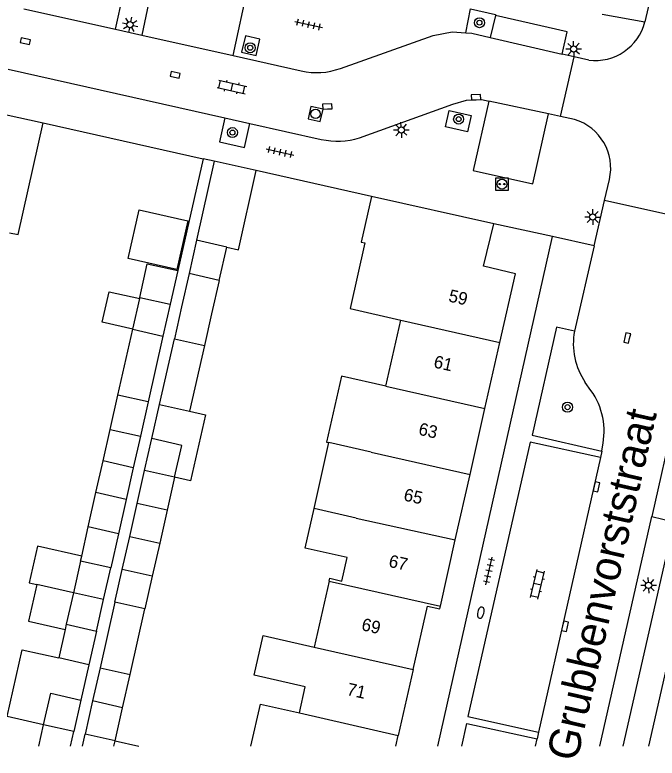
# Model space of a CAD drawing. Extents: x 128000 to 131008, y 398996 to 402500.
# Drawn here: x 128768.7 to 128820, y 398999 to 399058.4 of the extents above; entities that cross this region are included whole.
import ezdxf

# ---------------------------------------------------------------- set-up
doc = ezdxf.new("R2010")
doc.units = 0
for name, color, linetype in [('gg-afsc-muur', 7, 'Continuous'), ('gg-anno-huisnummerreeks BGT', 7, 'Continuous'), ('gg-anno-openbare ruimte label', 7, 'Continuous'), ('gg-bbg-bijgebouw', 7, 'Continuous'), ('gg-bbg-gedigitaliseerde bebouwing', 7, 'Continuous'), ('gg-bbg-gedigitaliseerde bijgebouw', 7, 'Continuous'), ('gg-bbg-hoofdgebouw', 7, 'Continuous'), ('gg-bbg-luifel en loopbrug', 7, 'Continuous'), ('gg-bbg-tussenscheiding', 7, 'Continuous'), ('gg-knt-verharding', 7, 'Continuous'), ('gg-knt-verharding nz', 7, 'Continuous'), ('gt-grn-weggrens', 7, 'Continuous'), ('gt-symb-boom', 7, 'Continuous'), ('gt-symb-brandkraan', 7, 'Continuous'), ('gt-symb-klinker verharding', 7, 'Continuous'), ('gt-symb-kolk', 7, 'Continuous'), ('gt-symb-laadpunt elektrisch vervoer', 7, 'Continuous'), ('gt-symb-lichtmast', 7, 'Continuous'), ('gt-symb-rioolschacht', 7, 'Continuous'), ('gt-symb-tegel verharding', 7, 'Continuous')]:
    doc.layers.add(name, color=color, linetype=linetype)

# ---------------------------------------------------------------- blocks, each defined once
blk = doc.blocks.new('gt0-TEG1')
at = {"layer": 'gt-symb-tegel verharding'}
for p, q in [((-1.125, 0), (1.125, 0)), ((-0.9, -0.25), (-0.9, 0.25)), ((-0.45, -0.25), (-0.45, 0.25)), ((0, -0.25), (0, 0.25)), ((0.45, -0.25), (0.45, 0.25)), ((0.9, -0.25), (0.9, 0.25))]:
    blk.add_line(p, q, dxfattribs=at)
blk = doc.blocks.new('gt0-BOOM')
at = {"layer": 'gt-symb-boom'}
for radius in [0.4, 0.2]:
    blk.add_circle((0, 0), radius, dxfattribs=at)
blk = doc.blocks.new('gt0-LMAST')
at = {"layer": 'gt-symb-lichtmast'}
for p, q in [((-0.005, 0.246), (-0.005, 0.621)), ((-0.182, 0.173), (-0.447, 0.438)), ((0.172, 0.173), (0.437, 0.438)), ((-0.255, -0.004), (-0.63, -0.004)), ((-0.182, -0.181), (-0.447, -0.446)), ((-0.005, -0.254), (-0.005, -0.629)), ((0.437, -0.446), (0.172, -0.181)), ((0.245, -0.004), (0.62, -0.004))]:
    blk.add_line(p, q, dxfattribs=at)
blk.add_circle((-0.005, -0.004), 0.25, dxfattribs=at)
blk = doc.blocks.new('gt0-KOLK')
at = {"layer": 'gt-symb-kolk'}
blk.add_lwpolyline([(0, 0), (0.375, 0), (0.375, 0.4), (-0.375, 0.4), (-0.375, 0), (0, 0)], dxfattribs=at)
blk = doc.blocks.new('gt0-BR')
at = {"layer": 'gt-symb-brandkraan'}
for centre, radius, start, end in [((-0.244, 0), 0.206, 107.56694, 252.43307), ((0.599, -2.664), 3, 106.89205, 107.56694), ((0, -0.691), 0.938, 73.10799, 106.89205), ((-0.599, -2.664), 3, 72.43309, 73.10799), ((0.244, 0), 0.206, 287.56695, 72.43309), ((0.599, 2.664), 3, 252.43307, 253.10797), ((0, 0.691), 0.938, 253.10797, 286.89206), ((-0.599, 2.664), 3, 286.89206, 287.56695)]:
    blk.add_arc(centre, radius, start, end, dxfattribs=at)
blk = doc.blocks.new('gt0-KL1')
at = {"layer": 'gt-symb-klinker verharding'}
for p, q in [((-1.15, 0.3), (1.15, 0.3)), ((-1, -0.3), (-1, 0.3)), ((-0.5, 0.3), (-0.5, 0.45)), ((0, -0.3), (0, 0.3)), ((0.5, 0.3), (0.5, 0.45)), ((1, -0.3), (1, 0.3)), ((-1.15, -0.3), (1.15, -0.3)), ((-0.5, -0.45), (-0.5, -0.3)), ((0.5, -0.45), (0.5, -0.3))]:
    blk.add_line(p, q, dxfattribs=at)
blk = doc.blocks.new('gt0-LEV')
at = {"layer": 'gt-symb-laadpunt elektrisch vervoer'}
blk.add_lwpolyline([(-0.486, 0.501), (0.486, 0.501), (0.486, -0.499), (-0.486, -0.499)], close=True, dxfattribs=at)
for centre, radius in [((0, 0), 0.393), ((-0.186, 0), 0.0566), ((0.186, 0), 0.0566)]:
    blk.add_circle(centre, radius, dxfattribs=at)
blk = doc.blocks.new('gt0-RS')
at = {"layer": 'gt-symb-rioolschacht'}
blk.add_lwpolyline([(-0.5, -0.5), (0.5, -0.5), (0.5, 0.5), (-0.5, 0.5)], close=True, dxfattribs=at)
blk.add_circle((0, 0), 0.375, dxfattribs=at)

msp = doc.modelspace()

# ---------------------------------------------------------------- linework, layer by layer
at = {"layer": 'gg-afsc-muur'}
for p, q in [((128770.991, 399049.778), (128783.786, 399046.917)), ((128783.786, 399046.917), (128781.753, 399037.979)), ((128797.228, 399043.912), (128788.016, 399045.971))]:
    msp.add_line(p, q, dxfattribs=at)
at = {"layer": 'gg-bbg-bijgebouw'}
for p, q in [((128783.25, 399040.401), (128782.652, 399037.742)), ((128785.66, 399039.851), (128783.25, 399040.401)), ((128785.057, 399037.196), (128785.66, 399039.851)), ((128778.164, 399033.305), (128778.713, 399035.744)), ((128778.713, 399035.744), (128778.733, 399035.832)), ((128778.733, 399035.832), (128781.141, 399035.29)), ((128781.141, 399035.29), (128780.57, 399032.754)), ((128780.295, 399027.292), (128781.482, 399032.547)), ((128783.88, 399032.005), (128782.695, 399026.755)), ((128780.295, 399027.292), (128782.695, 399026.755)), ((128775.791, 399022.779), (128776.358, 399025.294)), ((128776.358, 399025.294), (128778.766, 399024.751)), ((128778.766, 399024.751), (128778.199, 399022.236)), ((128779.107, 399022.031), (128779.678, 399024.562)), ((128775.222, 399020.254), (128775.791, 399022.779)), ((128778.199, 399022.236), (128777.63, 399019.711)), ((128778.51, 399019.387), (128779.107, 399022.031)), ((128781.504, 399021.485), (128780.908, 399018.845)), ((128777.63, 399019.711), (128775.222, 399020.254)), ((128780.908, 399018.845), (128778.51, 399019.387)), ((128773.99, 399014.784), (128773.421, 399012.259)), ((128776.398, 399014.242), (128773.99, 399014.784)), ((128775.829, 399011.718), (128776.398, 399014.242)), ((128776.728, 399011.499), (128777.32, 399014.121)), ((128779.719, 399013.583), (128777.32, 399014.121)), ((128779.719, 399013.583), (128779.127, 399010.96)), ((128773.421, 399012.259), (128772.852, 399009.734)), ((128775.26, 399009.192), (128775.829, 399011.718)), ((128772.852, 399009.734), (128775.26, 399009.192)), ((128774.019, 399003.684), (128773.452, 399001.168)), ((128774.948, 399003.618), (128774.349, 399000.967)), ((128777.35, 399003.077), (128774.948, 399003.618)), ((128776.753, 399000.428), (128777.35, 399003.077)), ((128770.658, 399000), (128771.043, 399001.707)), ((128773.189, 399000), (128773.452, 399001.168)), ((128774.131, 399000), (128774.349, 399000.967)), ((128776.657, 399000), (128776.753, 399000.428))]:
    msp.add_line(p, q, dxfattribs=at)
for points in [[(128782.652, 399037.742), (128782.054, 399035.082), (128781.482, 399032.547)], [(128785.057, 399037.196), (128784.453, 399034.54), (128783.88, 399032.005)], [(128781.504, 399021.485), (128782.077, 399024.02), (128779.678, 399024.562)], [(128771.043, 399001.707), (128771.611, 399004.226), (128774.019, 399003.684)]]:
    msp.add_lwpolyline(points, dxfattribs=at)
at = {"layer": 'gg-bbg-gedigitaliseerde bebouwing'}
for p, q in [((128798.376, 399028.765), (128799.563, 399034.028)), ((128792.633, 399018.979), (128793.815, 399024.249)), ((128793.835, 399013.176), (128792.649, 399007.923))]:
    msp.add_line(p, q, dxfattribs=at)
for points in [[(128798.376, 399028.765), (128794.822, 399029.559), (128793.64, 399024.288), (128793.815, 399024.249)], [(128793.835, 399013.176), (128793.887, 399013.408), (128794.862, 399013.188), (128795.287, 399015.074), (128791.927, 399015.828), (128792.633, 399018.979)], [(128791.462, 399002.661), (128791.933, 399004.751), (128787.851, 399005.666), (128788.563, 399008.839), (128792.649, 399007.923)], [(128787.589, 399000), (128788.351, 399003.365), (128791.462, 399002.661)]]:
    msp.add_lwpolyline(points, dxfattribs=at)
at = {"layer": 'gg-bbg-gedigitaliseerde bijgebouw'}
for p, q in [((128776.979, 399028.048), (128778.164, 399033.305)), ((128780.57, 399032.754), (128779.387, 399027.505)), ((128779.387, 399027.505), (128776.979, 399028.048)), ((128773.421, 399012.259), (128770.494, 399012.918)), ((128776.728, 399011.499), (128775.547, 399006.268)), ((128777.947, 399005.726), (128779.127, 399010.96)), ((128772.852, 399009.734), (128772.762, 399009.332)), ((128775.547, 399006.268), (128777.947, 399005.726))]:
    msp.add_line(p, q, dxfattribs=at)
msp.add_lwpolyline([(128770.494, 399012.918), (128769.835, 399009.991), (128772.762, 399009.332)], dxfattribs=at)
at = {"layer": 'gg-bbg-hoofdgebouw'}
for p, q in [((128806.986, 399041.723), (128797.228, 399043.912)), ((128806.285, 399026.979), (128807.472, 399032.238)), ((128805.096, 399021.71), (128806.285, 399026.979)), ((128803.913, 399016.47), (128805.096, 399021.71)), ((128802.722, 399011.192), (128803.913, 399016.47)), ((128800.548, 399006.115), (128799.358, 399000.857)), ((128799.164, 399000), (128799.358, 399000.857))]:
    msp.add_line(p, q, dxfattribs=at)
for points in [[(128797.228, 399043.912), (128796.41, 399040.263), (128796.693, 399040.199), (128795.514, 399034.944), (128799.563, 399034.028)], [(128807.472, 399032.238), (128808.71, 399037.721), (128806.172, 399038.33), (128806.986, 399041.723)], [(128800.548, 399006.115), (128801.694, 399011.18), (128802.67, 399010.961), (128802.722, 399011.192)]]:
    msp.add_lwpolyline(points, dxfattribs=at)
at = {"layer": 'gg-bbg-luifel en loopbrug'}
for p, q in [((128767.98, 399050.451), (128770.991, 399049.778)), ((128784.664, 399046.721), (128783.25, 399040.401)), ((128788.016, 399045.971), (128784.664, 399046.721)), ((128781.753, 399037.979), (128781.141, 399035.29)), ((128776.358, 399025.294), (128776.979, 399028.048)), ((128779.387, 399027.505), (128778.766, 399024.751)), ((128779.678, 399024.562), (128780.295, 399027.292)), ((128774.605, 399017.515), (128775.222, 399020.254)), ((128777.63, 399019.711), (128777.013, 399016.973)), ((128777.913, 399016.743), (128778.51, 399019.387)), ((128780.908, 399018.845), (128780.312, 399016.206)), ((128774.08, 399015.186), (128774.605, 399017.515)), ((128777.013, 399016.973), (128774.605, 399017.515)), ((128777.013, 399016.973), (128776.398, 399014.242)), ((128777.32, 399014.121), (128777.913, 399016.743)), ((128777.913, 399016.743), (128780.312, 399016.206)), ((128780.312, 399016.206), (128779.719, 399013.583)), ((128773.99, 399014.784), (128774.08, 399015.186)), ((128772.762, 399009.332), (128772.246, 399007.045)), ((128775.26, 399009.192), (128774.654, 399006.503)), ((128774.654, 399006.503), (128772.246, 399007.045)), ((128774.654, 399006.503), (128774.019, 399003.684)), ((128775.547, 399006.268), (128774.948, 399003.618)), ((128777.35, 399003.077), (128777.947, 399005.726)), ((128776.753, 399000.428), (128778.648, 399000))]:
    msp.add_line(p, q, dxfattribs=at)
for points in [[(128768.319, 399041.011), (128769.002, 399040.859), (128770.991, 399049.778)], [(128785.66, 399039.851), (128786.597, 399039.637), (128788.016, 399045.971)], [(128777.783, 399038.946), (128778.662, 399042.848), (128782.564, 399041.97), (128781.686, 399038.067), (128777.783, 399038.946)], [(128778.733, 399035.832), (128779.314, 399038.528), (128781.753, 399037.979)], [(128778.164, 399033.305), (128775.725, 399033.854), (128776.274, 399036.293), (128778.713, 399035.744)], [(128782.695, 399026.755), (128783.962, 399026.467), (128782.766, 399021.198), (128781.504, 399021.485)], [(128774.08, 399015.186), (128770.545, 399015.982), (128769.886, 399013.055), (128770.494, 399012.918)], [(128771.043, 399001.707), (128768.116, 399002.366), (128769.319, 399007.705), (128772.246, 399007.045)]]:
    msp.add_lwpolyline(points, dxfattribs=at)
at = {"layer": 'gg-bbg-tussenscheiding'}
for p, q in [((128785.057, 399037.196), (128782.652, 399037.742)), ((128799.563, 399034.028), (128807.472, 399032.238)), ((128778.164, 399033.305), (128780.57, 399032.754)), ((128781.482, 399032.547), (128783.88, 399032.005)), ((128798.376, 399028.765), (128806.285, 399026.979)), ((128797.186, 399023.493), (128793.815, 399024.249)), ((128797.186, 399023.493), (128805.096, 399021.71)), ((128778.199, 399022.236), (128775.791, 399022.779)), ((128781.504, 399021.485), (128779.107, 399022.031)), ((128795.997, 399018.221), (128792.633, 399018.979)), ((128795.997, 399018.221), (128803.913, 399016.47)), ((128793.835, 399013.176), (128802.722, 399011.192)), ((128775.829, 399011.718), (128773.421, 399012.259)), ((128779.127, 399010.96), (128776.728, 399011.499)), ((128792.649, 399007.923), (128800.548, 399006.115)), ((128791.462, 399002.661), (128799.358, 399000.857)), ((128773.452, 399001.168), (128771.043, 399001.707)), ((128776.753, 399000.428), (128774.349, 399000.967))]:
    msp.add_line(p, q, dxfattribs=at)
at = {"layer": 'gg-knt-verharding'}
for p, q in [((128819.523, 399059.897), (128819.059, 399057.84)), ((128807.114, 399058.351), (128806.709, 399056.602)), ((128776.787, 399057.259), (128778.88, 399056.79)), ((128813.415, 399055.057), (128812.462, 399055.277)), ((128786.167, 399055.159), (128791.61, 399053.941)), ((128812.324, 399050.28), (128813.415, 399055.057)), ((128814.57, 399054.791), (128813.415, 399055.057)), ((128768.2, 399054.058), (128785.505, 399050.185)), ((128812.324, 399050.28), (128811.355, 399050.49)), ((128785.505, 399050.185), (128787.51, 399049.736)), ((128813.44, 399050.039), (128812.324, 399050.28)), ((128787.51, 399049.736), (128793.21, 399048.46)), ((128815.834, 399043.594), (128816.22, 399045.261)), ((128814.995, 399039.966), (128815.834, 399043.594)), ((128820.734, 399042.491), (128815.834, 399043.594)), ((128811.69, 399040.711), (128806.986, 399041.723)), ((128802.517, 399000), (128811.69, 399040.711)), ((128814.995, 399039.966), (128813.427, 399033.157)), ((128819.373, 399000), (128828.18, 399039.041)), ((128814.75, 399028.409), (128814.29, 399029.051)), ((128821.391, 399026.279), (128819.598, 399018.34)), ((128815.618, 399023.575), (128815.66, 399023.901)), ((128815.618, 399023.575), (128815.518, 399023.044)), ((128810.31, 399000), (128810.451, 399000.597)), ((128810.55, 399001.11), (128810.451, 399000.597))]:
    msp.add_line(p, q, dxfattribs=at)
for points in [[(128776.787, 399057.259), (128778, 399062.828), (128770.681, 399064.475), (128769.872, 399060.763)], [(128786.167, 399055.159), (128787.379, 399060.718), (128780.066, 399062.377), (128778.88, 399056.79)], [(128804.745, 399056.972), (128805.137, 399058.884), (128807.136, 399058.446), (128807.114, 399058.351)], [(128812.462, 399055.277), (128812.858, 399057.055), (128807.114, 399058.351)], [(128794.739, 399054.13), (128802.15, 399056.771), (128803.66, 399057.041), (128804.745, 399056.972)], [(128804.745, 399056.972), (128805.24, 399056.941), (128806.709, 399056.602)], [(128786.854, 399055.42), (128788.009, 399055.153), (128788.316, 399056.457), (128787.161, 399056.724), (128786.854, 399055.42)], [(128796.27, 399048.581), (128803.71, 399051.281), (128804.8, 399051.601), (128806.03, 399051.641), (128806.591, 399051.52)], [(128806.591, 399051.52), (128805.344, 399045.966), (128810.105, 399044.902), (128811.355, 399050.49)], [(128803.136, 399049.46), (128803.435, 399050.771), (128805.178, 399050.373), (128804.879, 399049.062), (128803.136, 399049.46)], [(128785.505, 399050.185), (128785.076, 399048.275), (128787.088, 399047.824), (128787.51, 399049.736)], [(128813.427, 399033.157), (128811.989, 399033.478), (128810.052, 399024.85), (128815.618, 399023.575)], [(128815.518, 399023.044), (128809.906, 399024.28), (128804.926, 399002.365), (128810.55, 399001.11)], [(128819.598, 399018.34), (128821.363, 399017.931), (128817.307, 399000)], [(128804.435, 399000), (128804.846, 399001.826), (128810.451, 399000.597)]]:
    msp.add_lwpolyline(points, dxfattribs=at)
for centre, radius, start, end in [((128815.078, 399058.872), 4.112, 262.89769, 345.47225), ((128792.866, 399059.137), 5.345, 256.40618, 290.50706), ((128812.297, 399046.176), 4.028, 346.86551, 73.51904), ((128794.512, 399054.288), 5.971, 257.4061, 287.12277), ((128818.931, 399032.17), 5.592, 169.83497, 213.90437), ((128810.221, 399025.149), 5.58, 347.07825, 35.74685)]:
    msp.add_arc(centre, radius, start, end, dxfattribs=at)
at = {"layer": 'gg-knt-verharding nz'}
for p, q in [((128769.466, 399058.897), (128776.787, 399057.259)), ((128778.88, 399056.79), (128786.167, 399055.159)), ((128806.709, 399056.602), (128812.462, 399055.277)), ((128811.355, 399050.49), (128806.591, 399051.52)), ((128815.518, 399023.044), (128810.55, 399001.11)), ((128815.455, 399000), (128819.598, 399018.34))]:
    msp.add_line(p, q, dxfattribs=at)
at = {"layer": 'gt-grn-weggrens'}
for p, q in [((128815.633, 399058.45), (128819.059, 399057.84)), ((128784.664, 399046.721), (128783.786, 399046.917)), ((128814.995, 399039.966), (128811.69, 399040.711))]:
    msp.add_line(p, q, dxfattribs=at)

# ---------------------------------------------------------------- block references
at = {"layer": 'gt-symb-boom'}
for p in [(128805.845, 399057.783), (128787.534, 399055.783), (128804.182, 399050.082), (128786.118, 399049.007), (128812.876, 399027.077)]:
    msp.add_blockref('gt0-BOOM', p, dxfattribs=at)
at = {"layer": 'gt-symb-brandkraan', "rotation": 77.3531465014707}
msp.add_blockref('gt0-BR', (128805.949, 399010.665), dxfattribs=at)
at = {"layer": 'gt-symb-klinker verharding'}
for p, rotation in [((128786.075, 399052.644), -12.646853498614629), ((128810.478, 399012.924), 76.7561979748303)]:
    msp.add_blockref('gt0-KL1', p, dxfattribs=dict(at, rotation=rotation))
at = {"layer": 'gt-symb-kolk'}
for p, rotation in [((128769.533, 399056.113), -12.715336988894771), ((128781.499, 399053.421), -12.715336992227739), ((128805.578, 399051.626), 1.8919654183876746), ((128793.705, 399050.894), 2.063819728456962), ((128817.837, 399032.555), 77.28466301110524), ((128814.997, 399020.761), -102.82712342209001), ((128812.487, 399009.62), -102.7027319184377)]:
    msp.add_blockref('gt0-KOLK', p, dxfattribs=dict(at, rotation=rotation))
at = {"layer": 'gt-symb-laadpunt elektrisch vervoer'}
msp.add_blockref('gt0-LEV', (128807.648, 399044.888), dxfattribs=at)
at = {"layer": 'gt-symb-lichtmast'}
for p, rotation in [((128777.95, 399057.619), -12.715336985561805), ((128813.372, 399055.687), 1.8919654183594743), ((128799.604, 399049.219), 1.8919654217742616), ((128819.352, 399012.853), 1.8919654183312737)]:
    msp.add_blockref('gt0-LMAST', p, dxfattribs=dict(at, rotation=rotation))
msp.add_blockref('gt0-LMAST', (128814.898, 399042.265), dxfattribs=at)
at = {"layer": 'gt-symb-rioolschacht', "rotation": -12.646853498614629}
msp.add_blockref('gt0-RS', (128792.755, 399050.494), dxfattribs=at)
at = {"layer": 'gt-symb-tegel verharding'}
for p, rotation in [((128792.204, 399057.637), -12.646853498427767), ((128789.919, 399047.449), -12.646853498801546), ((128806.602, 399013.996), 77.35314650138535)]:
    msp.add_blockref('gt0-TEG1', p, dxfattribs=dict(at, rotation=rotation))

# ---------------------------------------------------------------- texts
at = {"layer": 'gg-anno-huisnummerreeks BGT'}
for s, rotation, p in [('59', 347.3, (128803.317, 399035.526)), ('61', 347.3, (128802.128, 399030.259)), ('63', 347.3, (128800.917, 399024.89)), ('65', 347.3, (128799.731, 399019.636)), ('67', 347.3, (128798.535, 399014.338)), ('69', 347.2, (128796.365, 399009.276)), ('71', 347.2, (128795.194, 399004.105))]:
    msp.add_text(s, height=1, rotation=rotation, dxfattribs=at).set_placement(p)
at = {"layer": 'gg-anno-openbare ruimte label'}
msp.add_text('Grubbenvorststraat', height=2.5, rotation=77.1, dxfattribs=at).set_placement((128813.623, 398998.691))

doc.saveas('drawing.dxf')
